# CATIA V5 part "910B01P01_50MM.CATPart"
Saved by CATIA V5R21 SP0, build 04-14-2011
Part number: 910B01P01_50MM
Bounding box of the stored display mesh (mm): x -24.25 to 24.25, y -17.69 to 17.69, z -5 to 5
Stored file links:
  C:\Users\ALI OZGUN\Desktop\alhan\910B01P01_50MM.CATPart
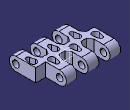
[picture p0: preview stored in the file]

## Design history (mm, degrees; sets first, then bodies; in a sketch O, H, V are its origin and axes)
Body1 (main body)
  Sketch1 on yz-plane, origin (0, 0, 0), H (0, 1, 0), V (0, 0, 1)
    construction line L1 (-12.7, 0) -> (12.7, 0)
    point P1 (-12.7, 0)
    point P2 (12.7, 0)
    line L2 (-12.7, 5) -> (12.7, 5)
    line L3 (12.7, -5) -> (-12.7, -5)
    arc A1 centre (12.7, 0) radius 5 from (12.7, 5) to (12.7, -5) cw
    arc A2 centre (-12.7, 0) radius 5 from (-12.7, -5) to (-12.7, 5) cw
    circle A3 centre (12.7, 0) radius 2.5
    circle A4 centre (-12.7, 0) radius 2.5
    distance L1 L2 = 5
    radius A3 = 2.5
    length L1 = 25.4
    distance P2 V = 12.7
    coincidence: P1 H
    horizontal: L1 H
    tangency: A1 L2, A2 L2, A1 L3, A2 L3
    symmetry: A3 A4 V
  Pad1: profile Sketch1, direction (1, 0, 0), length 24.25, mirrored extent
  Sketch2 on xy-plane, origin (0, 0, 0), H (1, 0, 0), V (0, 1, 0)
    line L1 (-16.25, 21.9078) -> (-16.25, 5.6641)
    line L2 (-16.25, 5.6641) -> (-14.25, 2.2)
    line L3 (-14.25, 2.2) -> (-9.75, 2.2)
    point P3 (-9.75, 2.2)
    line L4 (-9.75, 2.2) -> (-7.75, 5.6641)
    line L5 (-7.75, 5.6641) -> (-7.75, 21.9078)
    line L6 (-24.5, -18.5853) -> (-24.5, -5.6641)
    line L7 (-24.5, -5.6641) -> (-22.5, -2.2)
    line L8 (-22.5, -2.2) -> (-18, -2.2)
    point P7 (-18, -2.2)
    line L9 (-18, -2.2) -> (-16, -5.6641)
    line L10 (-16, -5.6641) -> (-16, -18.5853)
    reference projected line E1 (-24.25, 12.7) -> (-24.25, -12.7) from edge [start face of Pad1 | face of Pad1 from Sketch1.L2]
    reference projected line E2 (-24.25, 12.7) -> (-24.25, -12.7) from edge [start face of Pad1 | face of Pad1 from Sketch1.L2]
    construction line L11 (-20.25, -40.4005) -> (-20.25, 18.5197)
    axis line L12 (-12, 43.4801) -> (-12, -9.4971)
    reference projected line E3 through (0, -12.7) direction (1, 0) from axis of face of Pad1 from Sketch1.A2
    reference projected line E4 through (0, 12.7) direction (1, 0) from axis of face of Pad1 from Sketch1.A1
    line L13 (-16.25, 21.9078) -> (-7.75, 21.9078)
    line L14 (-24.5, -18.5853) -> (-16, -18.5853)
    distance L1 L5 = 8.5
    distance L1 E1 = 8
    distance L6 L10 = 8.5
    distance L6 E2 = 0.25
    distance L11 L10 = 4.25
    distance L12 L5 = 4.25
    angle L7 L6 = 150
    angle L9 L10 = 150
    distance L8 E3 = 10.5
    length L8 = 4.5
    distance P7 L11 = 2.25
    length L3 = 4.5
    distance P3 L12 = 2.25
    angle L2 L1 = 150
    angle L4 L5 = 150
    distance L3 E4 = 10.5
    vertical: L1 V, L5 V, L6 V, L10 V, L11 V, L12 V
    horizontal: L3 H, L8 H, L13 H, L14 H
  Pocket1: profile Sketch2, direction (0, 0, -1), length 24.25, mirrored extent
  RectPattern1: of Pocket1, direction 1 instances 3, spacing 16.5, along axis of face of Pad1 from Sketch1.A2
  RemoveFace1: RemoveFaces (face of RectPattern1; face of Pocket1 from Sketch2.L7; face of RectPattern1)
  Sketch3 on xy-plane, origin (0, 0, 0), H (1, 0, 0), V (0, 1, 0)
    arc A1 centre (-20.25, 2.7) radius 2.4 from (-22.5885, 3.24) to (-17.9115, 3.24) ccw
    point P1 (-20.25, 2.7)
    reference projected line E1 (-24.25, 12.7) -> (-24.25, -12.7) from edge [start face of Pad1 | face of Pad1 from Sketch1.L2]
    reference projected line E2 through (0, 12.7) direction (1, 0) from axis of face of Pad1 from Sketch1.A1
    arc A2 centre (-20.25, 6.7) radius 1.5 from (-18.7885, 7.0375) to (-21.7115, 7.0375) ccw
    point P2 (-20.25, 6.7)
    line L1 (-18.7885, 7.0375) -> (-17.9115, 3.24)
    line L2 (-21.7115, 7.0375) -> (-22.5885, 3.24)
    reference projected line E3 (-24.25, 12.7) -> (-24.25, -12.7) from edge [start face of Pad1 | face of Pad1 from Sketch1.L2]
    arc A3 centre (-11.75, -2.6) radius 2.4 from (-14.0885, -3.14) to (-9.4115, -3.14) cw
    arc A4 centre (-11.75, -6.6) radius 1.5 from (-10.2885, -6.9375) to (-13.2115, -6.9375) cw
    line L3 (-10.2885, -6.9375) -> (-9.4115, -3.14)
    line L4 (-13.2115, -6.9375) -> (-14.0885, -3.14)
    radius A1 = 2.4
    distance E1 P1 = 4
    distance P1 E2 = 10
    radius A2 = 1.5
    distance A2 A1 = 7.9
    distance P2 E3 = 4
    tangency: L1 A2, L1 A1, L2 A2, L2 A1
  Pocket2: profile Sketch3, direction (0, 0, -1), length 24.25, mirrored extent
  RectPattern2: of Pocket2, direction 1 instances 3, spacing 16.5, along axis of face of Pad1 from Sketch1.A2
Body2
  Solid1: linked copy from another document
  Translate1: Direction zx-plane, Length 25.2, ToTransfor Solid1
